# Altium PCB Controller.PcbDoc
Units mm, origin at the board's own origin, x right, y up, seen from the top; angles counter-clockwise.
Board outline 154.94 x 111.76 mm, 2 copper layers (Top Layer, Bottom Layer); 187 components, 89 nets, 478 pads, 4 vias.
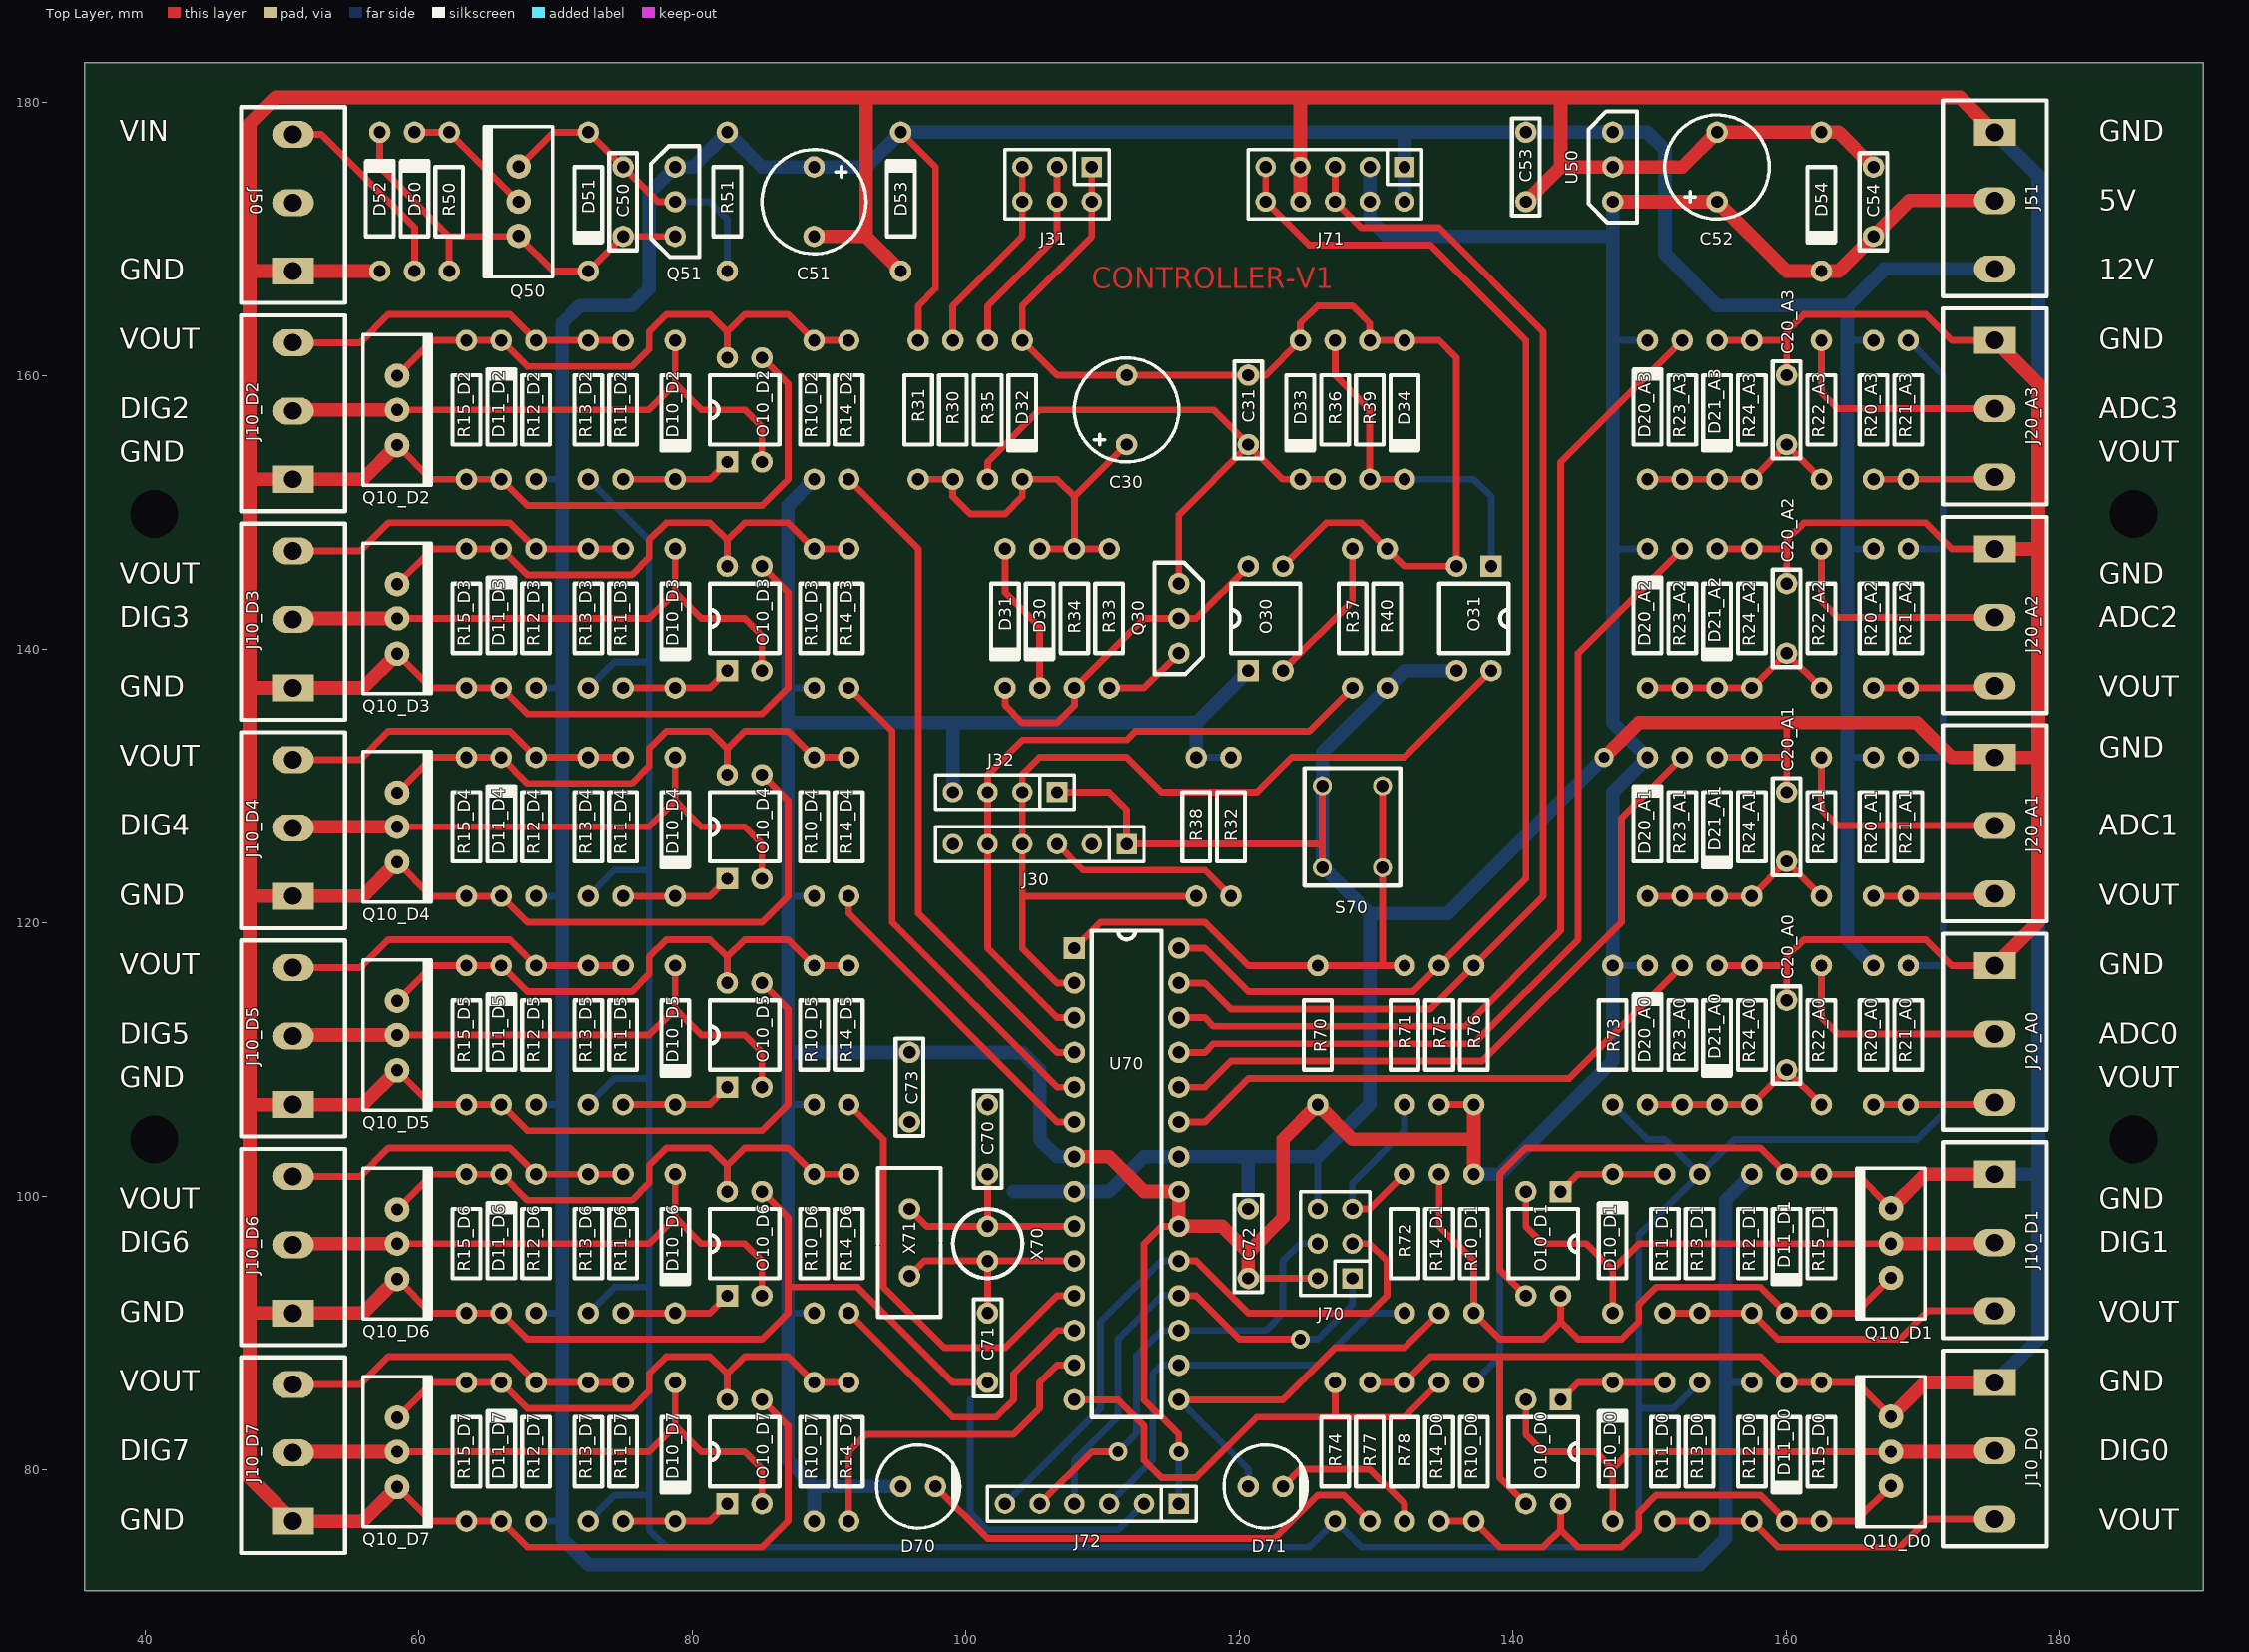
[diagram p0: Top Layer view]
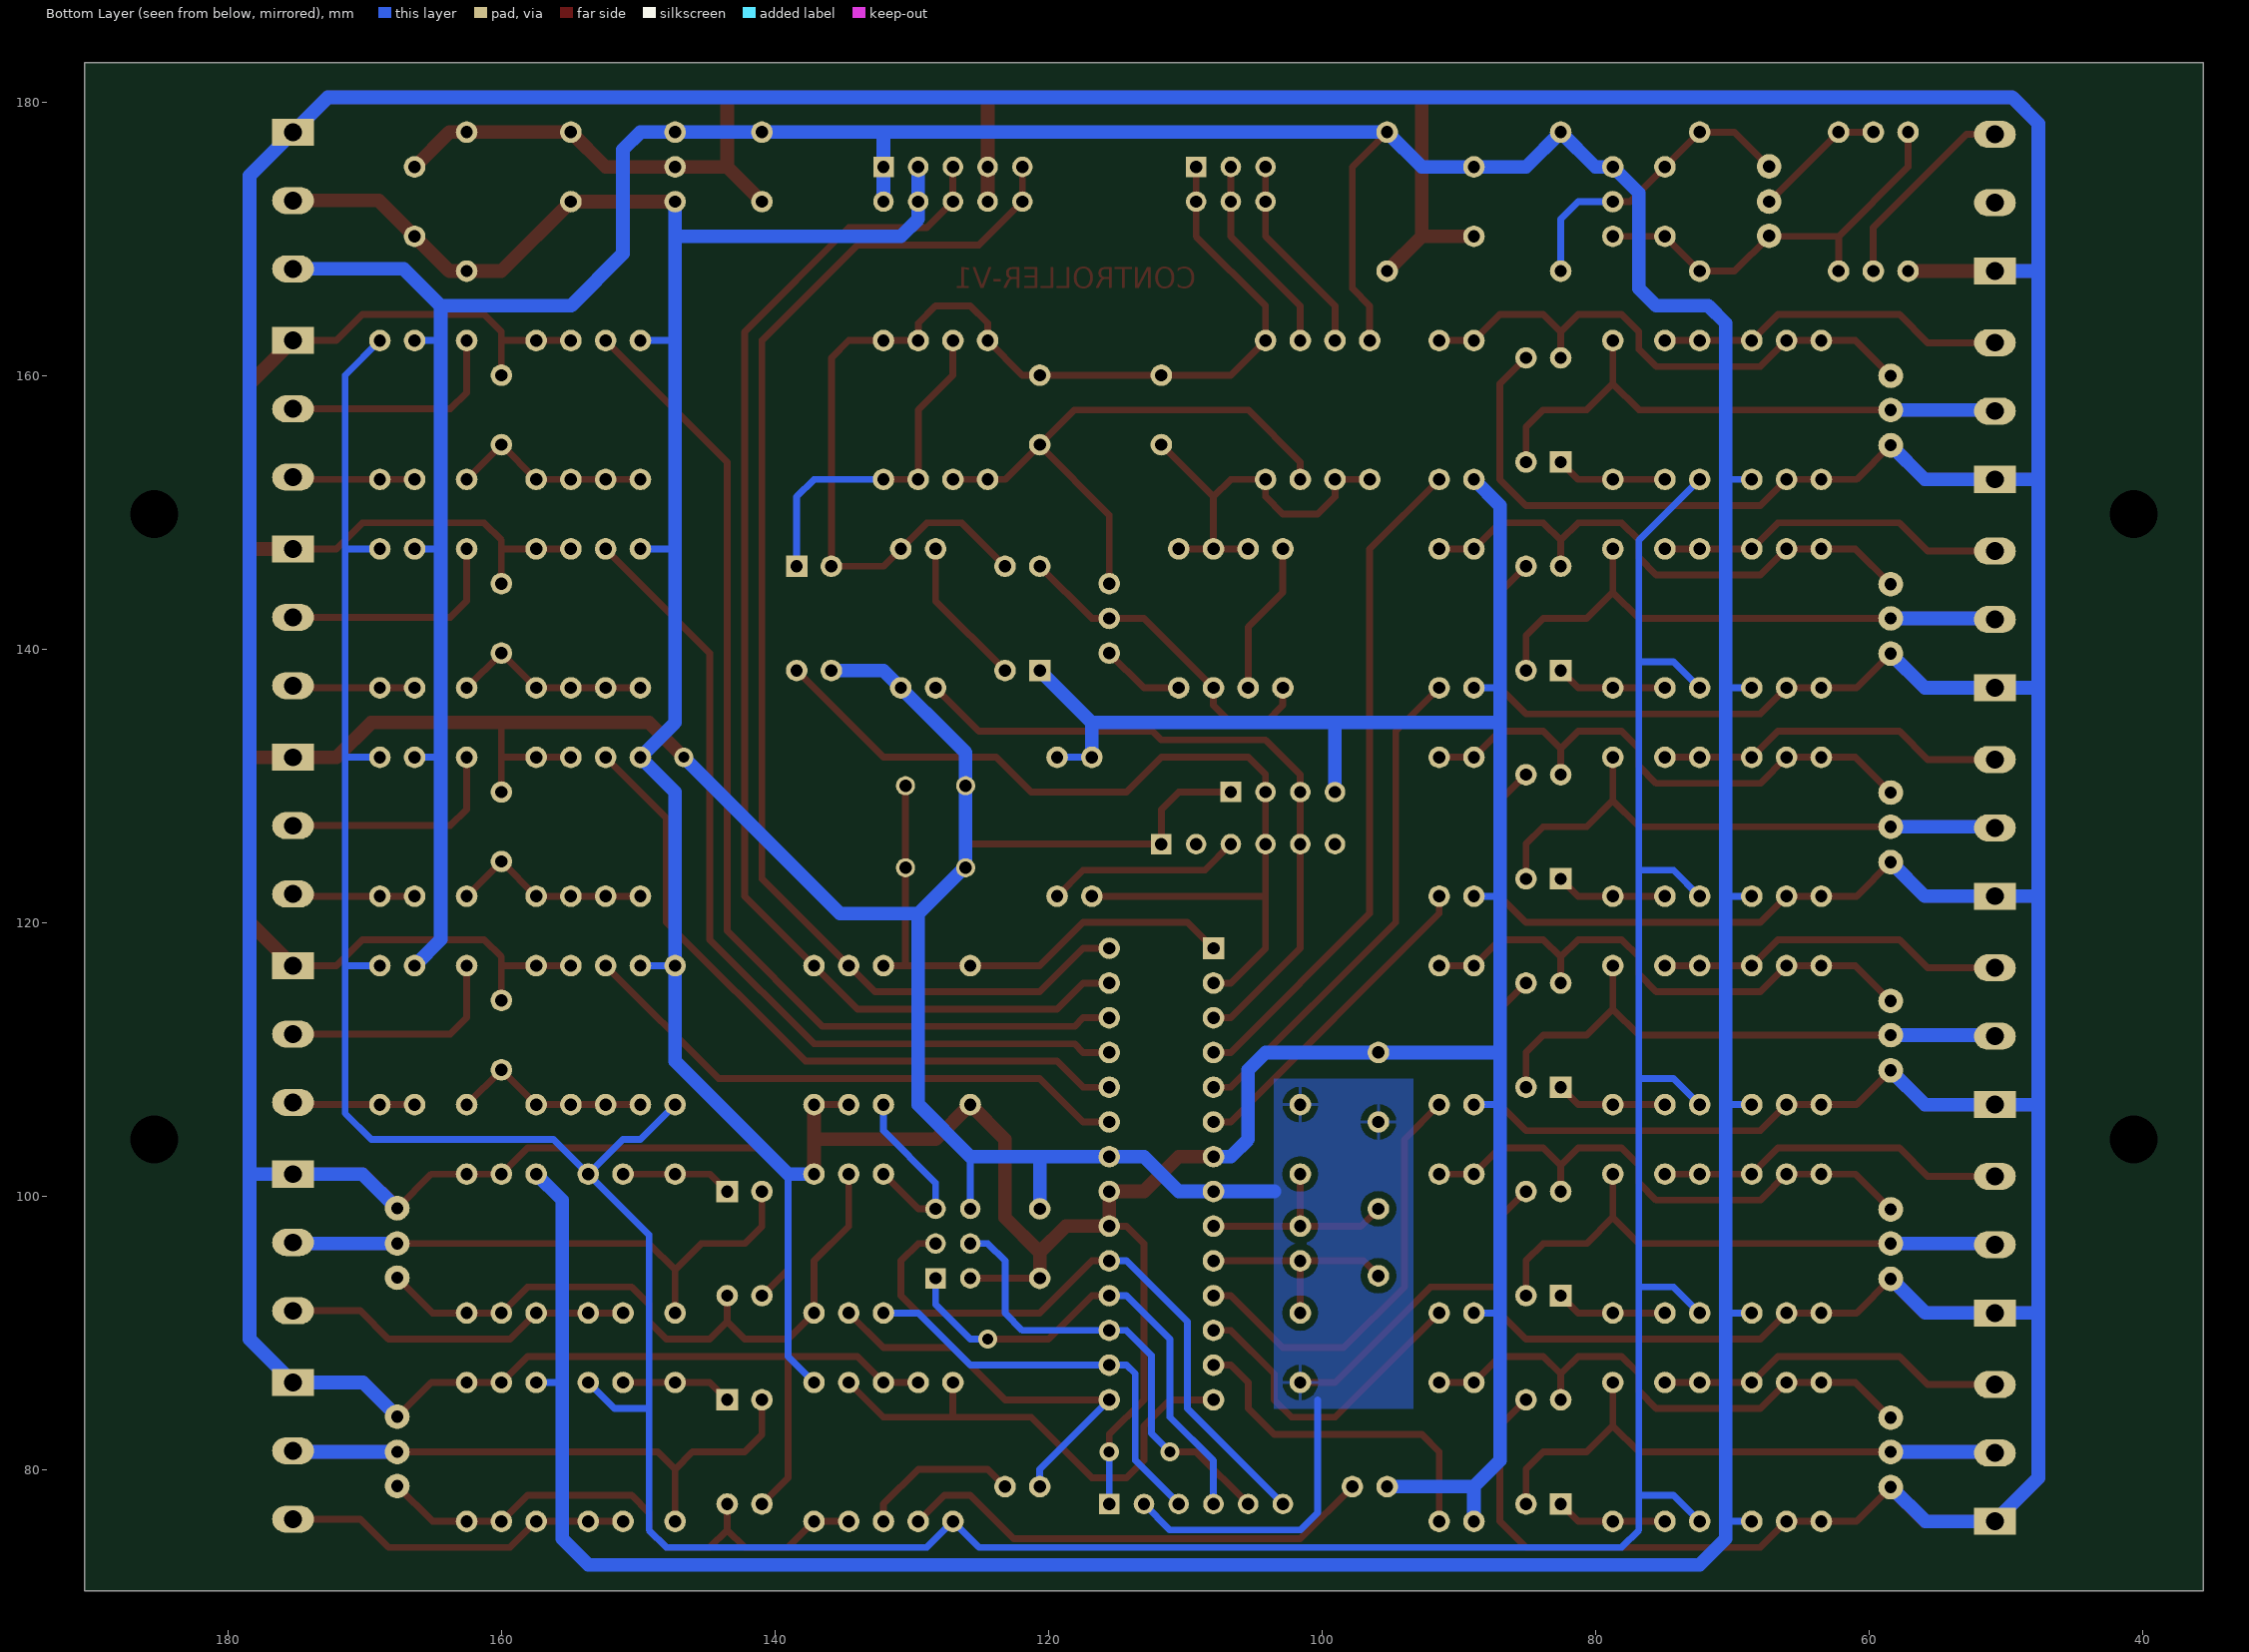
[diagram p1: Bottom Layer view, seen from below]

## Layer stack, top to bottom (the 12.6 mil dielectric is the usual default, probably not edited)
Top Layer: signal copper 0.0356
Dielectric: dielectric 0.32, FR-4, Dk 4.8
Bottom Layer: signal copper 0.0356

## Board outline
35.56,71.12 190.5,71.12 190.5,182.88 35.56,182.88

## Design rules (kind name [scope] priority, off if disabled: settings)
Clearance [All] p1: gap=0.5
ComponentClearance [All] p1: gap=0.127 collisioncheckmode=3 verticalgap=0.254
HoleSize [All] p1: absolutevalues=TRUE maxlimit=5 minlimit=0.025 maxpercent=80.000 minpercent=20.000
PolygonConnect [All] p1: connectstyle=Relief reliefconductorwidth=0.254 reliefentries=4 polygonreliefangle="90 Angle"
RoomDefinition M0 [InComponentClass('M0')] p1: confinementstyle=ConfineIn formatcopy=TRUE lockcomponents=FALSE outline 92.71,73.66 149.86,73.66 149.86,182.88 92.71,182.88
RoomDefinition P0 [InComponentClass('P0')] p2: confinementstyle=ConfineIn formatcopy=TRUE lockcomponents=FALSE outline 45.72,165.1 180.34,165.1 180.34,180.34 45.72,180.34
RoomDefinition A0 [InComponentClass('A0')] p3: confinementstyle=ConfineIn formatcopy=TRUE lockcomponents=FALSE outline 180.34,119.38 147.32,119.38 147.32,104.14 180.34,104.14
RoomDefinition A1 [InComponentClass('A1')] p4: confinementstyle=ConfineIn formatcopy=TRUE lockcomponents=FALSE outline 180.34,134.62 147.32,134.62 147.32,119.38 180.34,119.38
RoomDefinition A2 [InComponentClass('A2')] p5: confinementstyle=ConfineIn formatcopy=TRUE lockcomponents=FALSE outline 180.34,149.86 147.32,149.86 147.32,134.62 180.34,134.62
RoomDefinition A3 [InComponentClass('A3')] p6: confinementstyle=ConfineIn formatcopy=TRUE lockcomponents=FALSE outline 180.34,165.1 147.32,165.1 147.32,149.86 180.34,149.86
RoomDefinition D0 [InComponentClass('D0')] p7: confinementstyle=ConfineIn formatcopy=TRUE lockcomponents=FALSE outline 180.34,88.9 132.08,88.9 132.08,73.66 180.34,73.66
RoomDefinition D1 [InComponentClass('D1')] p8: confinementstyle=ConfineIn formatcopy=TRUE lockcomponents=FALSE outline 180.34,104.14 132.08,104.14 132.08,88.9 180.34,88.9
RoomDefinition D2 [InComponentClass('D2')] p9: confinementstyle=ConfineIn formatcopy=TRUE lockcomponents=FALSE outline 45.72,149.86 93.98,149.86 93.98,165.1 45.72,165.1
RoomDefinition D3 [InComponentClass('D3')] p10: confinementstyle=ConfineIn formatcopy=TRUE lockcomponents=FALSE outline 45.72,134.62 93.98,134.62 93.98,149.86 45.72,149.86
RoomDefinition D4 [InComponentClass('D4')] p11: confinementstyle=ConfineIn formatcopy=TRUE lockcomponents=FALSE outline 45.72,119.38 93.98,119.38 93.98,134.62 45.72,134.62
RoomDefinition D5 [InComponentClass('D5')] p12: confinementstyle=ConfineIn formatcopy=TRUE lockcomponents=FALSE outline 45.72,104.14 92.71,104.14 92.71,119.38 45.72,119.38
RoomDefinition D6 [InComponentClass('D6')] p13: confinementstyle=ConfineIn formatcopy=TRUE lockcomponents=FALSE outline 45.72,88.9 92.71,88.9 92.71,104.14 45.72,104.14
RoomDefinition D7 [InComponentClass('D7')] p14: confinementstyle=ConfineIn formatcopy=TRUE lockcomponents=FALSE outline 45.72,73.66 92.71,73.66 92.71,88.9 45.72,88.9
RoomDefinition C0 [InComponentClass('C0')] p15: confinementstyle=ConfineIn formatcopy=TRUE lockcomponents=FALSE outline 146.05,114.3 146.05,177.8 82.55,177.8 82.55,114.3
RoutingVias [All] p1: holewidth=0.8 width=1.4 viastyle="Through Hole" minholewidth=0.8 minwidth=1.4 maxholewidth=0.8 maxwidth=1.4
SolderMaskExpansion [All] p1: expansion=0.102
TestPointUsage [All] p1: valid=0 allowmultiple=FALSE
Testpoint [All] p1: side=15 testpointundercomponent=TRUE minsize=1.016 maxsize=2.54 preferedsize=1.524 minholesize=0 maxholesize=1.016 preferedholesize=0.813 testpointgrid=0.025 style=1023 order=0-112345678
Width [All] p1: maxlimit=5 minlimit=0.5 preferedwidth=0.5
17 further rules are at their usual default settings.

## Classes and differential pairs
component class P0: C50 C51 C52 C53 C54 D50 D51 D52 D53 D54 J50 J51 Q50 Q51 R50 R51 U50
component class M0: C70 C71 C72 C73 D70 D71 J70 J71 J72 R70 R71 R72 R73 R74 R75 R76 R77 R78 S70 U70 X70 X71
component class D7: D10_D7 D11_D7 J10_D7 O10_D7 Q10_D7 R10_D7 R11_D7 R12_D7 R13_D7 R14_D7 R15_D7
component class D6: D10_D6 D11_D6 J10_D6 O10_D6 Q10_D6 R10_D6 R11_D6 R12_D6 R13_D6 R14_D6 R15_D6
component class D5: D10_D5 D11_D5 J10_D5 O10_D5 Q10_D5 R10_D5 R11_D5 R12_D5 R13_D5 R14_D5 R15_D5
component class D4: D10_D4 D11_D4 J10_D4 O10_D4 Q10_D4 R10_D4 R11_D4 R12_D4 R13_D4 R14_D4 R15_D4
component class D3: D10_D3 D11_D3 J10_D3 O10_D3 Q10_D3 R10_D3 R11_D3 R12_D3 R13_D3 R14_D3 R15_D3
component class D2: D10_D2 D11_D2 J10_D2 O10_D2 Q10_D2 R10_D2 R11_D2 R12_D2 R13_D2 R14_D2 R15_D2
component class D1: D10_D1 D11_D1 J10_D1 O10_D1 Q10_D1 R10_D1 R11_D1 R12_D1 R13_D1 R14_D1 R15_D1
component class D0: D10_D0 D11_D0 J10_D0 O10_D0 Q10_D0 R10_D0 R11_D0 R12_D0 R13_D0 R14_D0 R15_D0
component class C0: C30 C31 D30 D31 D32 D33 D34 J30 J31 J32 O30 O31 Q30 R30 R31 R32 R33 R34 R35 R36 R37 R38 R39 R40
component class A3: C20_A3 D20_A3 D21_A3 J20_A3 R20_A3 R21_A3 R22_A3 R23_A3 R24_A3
component class A2: C20_A2 D20_A2 D21_A2 J20_A2 R20_A2 R21_A2 R22_A2 R23_A2 R24_A2
component class A1: C20_A1 D20_A1 D21_A1 J20_A1 R20_A1 R21_A1 R22_A1 R23_A1 R24_A1
component class A0: C20_A0 D20_A0 D21_A0 J20_A0 R20_A0 R21_A0 R22_A0 R23_A0 R24_A0
channel class Analog: A0 A1 A2 A3
channel class Digital: D0 D1 D2 D3 D4 D5 D6 D7

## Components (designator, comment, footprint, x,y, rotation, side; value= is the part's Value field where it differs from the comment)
C20_A0 "100N" AXIAL02 160.02,109.22 r90 top (schematic designator C20)
C20_A1 "100N" AXIAL02 160.02,124.46 r90 top (schematic designator C20)
C20_A2 "100N" AXIAL02 160.02,139.7 r90 top (schematic designator C20)
C20_A3 "100N" AXIAL02 160.02,154.94 r90 top (schematic designator C20)
C30 "10U" RADIAL02P 111.76,154.94 r90 top
C31 "100P" AXIAL02 120.65,154.94 r90 top
C50 "100N" AXIAL02 74.93,170.18 r90 top
C51 "10U" RADIAL02P 88.9,175.26 r270 top
C52 "10U" RADIAL02P 154.94,172.72 r90 top
C53 "100N" AXIAL02 140.97,177.8 r270 top
C54 "100N" AXIAL02 166.37,170.18 r90 top
C70 "18P" AXIAL02 101.6,101.6 r90 top
C71 "18P" AXIAL02 101.6,91.44 r270 top
C72 "100N" AXIAL02 120.65,93.98 r90 top
C73 "100N" AXIAL02 95.885,110.49 r270 top
D10_D0 "D-1N4148" DO35S 147.32,76.2 r90 top (schematic designator D10)
D10_D1 "D-1N4148" DO35S 147.32,91.44 r90 top (schematic designator D10)
D10_D2 "D-1N4148" DO35S 78.74,162.56 r270 top (schematic designator D10)
D10_D3 "D-1N4148" DO35S 78.74,147.32 r270 top (schematic designator D10)
D10_D4 "D-1N4148" DO35S 78.74,132.08 r270 top (schematic designator D10)
D10_D5 "D-1N4148" DO35S 78.74,116.84 r270 top (schematic designator D10)
D10_D6 "D-1N4148" DO35S 78.74,101.6 r270 top (schematic designator D10)
D10_D7 "D-1N4148" DO35S 78.74,86.36 r270 top (schematic designator D10)
D11_D0 "5V6" DO35S 160.02,86.36 r270 top (schematic designator D11)
D11_D1 "5V6" DO35S 160.02,101.6 r270 top (schematic designator D11)
D11_D2 "5V6" DO35S 66.04,152.4 r90 top (schematic designator D11)
D11_D3 "5V6" DO35S 66.04,137.16 r90 top (schematic designator D11)
D11_D4 "5V6" DO35S 66.04,121.92 r90 top (schematic designator D11)
D11_D5 "5V6" DO35S 66.04,106.68 r90 top (schematic designator D11)
D11_D6 "5V6" DO35S 66.04,91.44 r90 top (schematic designator D11)
D11_D7 "5V6" DO35S 66.04,76.2 r90 top (schematic designator D11)
D20_A0 "D-1N4148" DO35S 149.86,106.68 r90 top (schematic designator D20)
D20_A1 "D-1N4148" DO35S 149.86,121.92 r90 top (schematic designator D20)
D20_A2 "D-1N4148" DO35S 149.86,137.16 r90 top (schematic designator D20)
D20_A3 "D-1N4148" DO35S 149.86,152.4 r90 top (schematic designator D20)
D21_A0 "D-1N4148" DO35S 154.94,116.84 r270 top (schematic designator D21)
D21_A1 "D-1N4148" DO35S 154.94,132.08 r270 top (schematic designator D21)
D21_A2 "D-1N4148" DO35S 154.94,147.32 r270 top (schematic designator D21)
D21_A3 "D-1N4148" DO35S 154.94,162.56 r270 top (schematic designator D21)
D30 "D-1N4148" DO35S 105.41,147.32 r270 top
D31 "D-1N4148" DO35S 102.87,147.32 r270 top
D32 "15V" DO35S 104.14,162.56 r270 top
D33 "5V6" DO35S 124.46,162.56 r270 top
D34 "D-1N4148" DO35S 132.08,162.56 r270 top
D50 "D-1N4001" DO35S 59.69,167.64 r90 top
D51 "12V" DO35S 72.39,177.8 r270 top
D52 "15V" DO35S 57.15,167.64 r90 top
D53 "15V" DO35S 95.25,167.64 r90 top
D54 "5V6" DO35S 162.56,177.8 r270 top
D70 "RED" LED5MM 96.52,78.74 r0 top
D71 "AMBER" LED5MM 121.92,78.74 r0 top
J10_D0 "TERM" MKD500S3 175.26,86.36 r270 top (schematic designator J10)
J10_D1 "TERM" MKD500S3 175.26,101.6 r270 top (schematic designator J10)
J10_D2 "TERM" MKD500S3 50.8,152.4 r90 top (schematic designator J10)
J10_D3 "TERM" MKD500S3 50.8,137.16 r90 top (schematic designator J10)
J10_D4 "TERM" MKD500S3 50.8,121.92 r90 top (schematic designator J10)
J10_D5 "TERM" MKD500S3 50.8,106.68 r90 top (schematic designator J10)
J10_D6 "TERM" MKD500S3 50.8,91.44 r90 top (schematic designator J10)
J10_D7 "TERM" MKD500S3 50.8,76.2 r90 top (schematic designator J10)
J20_A0 "TERM" MKD500S3 175.26,116.84 r270 top (schematic designator J20)
J20_A1 "TERM" MKD500S3 175.26,132.08 r270 top (schematic designator J20)
J20_A2 "TERM" MKD500S3 175.26,147.32 r270 top (schematic designator J20)
J20_A3 "TERM" MKD500S3 175.26,162.56 r270 top (schematic designator J20)
J30 "HDR1X6" HDR6X1 111.76,125.73 r180 top
J31 "HDR3X2" HDR3X2 109.22,175.26 r180 top
J32 "HDR1X4" HDR4X1 106.68,129.54 r180 top
J50 "TERM" MKD500S3 50.8,167.64 r90 top
J51 "TERM" MKD500S3 175.26,177.8 r270 top
J70 "HDR3X2" HDR3X2 128.27,93.98 r90 top
J71 "HDR5X2" HDR5X2 132.08,175.26 r180 top
J72 "HDR1X6" HDR6X1 115.57,77.47 r180 top
O10_D0 "FOD817B" DIP4 143.51,85.09 r270 top (schematic designator O10)
O10_D1 "FOD817B" DIP4 143.51,100.33 r270 top (schematic designator O10)
O10_D2 "FOD817B" DIP4 82.55,153.67 r90 top (schematic designator O10)
O10_D3 "FOD817B" DIP4 82.55,138.43 r90 top (schematic designator O10)
O10_D4 "FOD817B" DIP4 82.55,123.19 r90 top (schematic designator O10)
O10_D5 "FOD817B" DIP4 82.55,107.95 r90 top (schematic designator O10)
O10_D6 "FOD817B" DIP4 82.55,92.71 r90 top (schematic designator O10)
O10_D7 "FOD817B" DIP4 82.55,77.47 r90 top (schematic designator O10)
O30 "FOD817B" DIP4 120.65,138.43 r90 top
O31 "FOD817B" DIP4 138.43,146.05 r270 top
Q10_D0 "FQPF10N20C" TO220V 167.64,81.28 r90 top (schematic designator Q10)
Q10_D1 "FQPF10N20C" TO220V 167.64,96.52 r90 top (schematic designator Q10)
Q10_D2 "FQPF10N20C" TO220V 58.42,157.48 r270 top (schematic designator Q10)
Q10_D3 "FQPF10N20C" TO220V 58.42,142.24 r270 top (schematic designator Q10)
Q10_D4 "FQPF10N20C" TO220V 58.42,127 r270 top (schematic designator Q10)
Q10_D5 "FQPF10N20C" TO220V 58.42,111.76 r270 top (schematic designator Q10)
Q10_D6 "FQPF10N20C" TO220V 58.42,96.52 r270 top (schematic designator Q10)
Q10_D7 "FQPF10N20C" TO220V 58.42,81.28 r270 top (schematic designator Q10)
Q30 "Q-BC558" TO92 115.57,139.7 r90 top
Q50 "FQPF10N20C" TO220V 67.31,172.72 r90 top
Q51 "BC548" TO92 78.74,175.26 r270 top
R10_D0 "4K7" AXIAL04 137.16,76.2 r90 top (schematic designator R10)
R10_D1 "4K7" AXIAL04 137.16,91.44 r90 top (schematic designator R10)
R10_D2 "4K7" AXIAL04 88.9,162.56 r270 top (schematic designator R10)
R10_D3 "4K7" AXIAL04 88.9,147.32 r270 top (schematic designator R10)
R10_D4 "4K7" AXIAL04 88.9,132.08 r270 top (schematic designator R10)
R10_D5 "4K7" AXIAL04 88.9,116.84 r270 top (schematic designator R10)
R10_D6 "4K7" AXIAL04 88.9,101.6 r270 top (schematic designator R10)
R10_D7 "4K7" AXIAL04 88.9,86.36 r270 top (schematic designator R10)
R11_D0 "33R" AXIAL04 151.13,86.36 r270 top (schematic designator R11)
R11_D1 "33R" AXIAL04 151.13,101.6 r270 top (schematic designator R11)
R11_D2 "33R" AXIAL04 74.93,152.4 r90 top (schematic designator R11)
R11_D3 "33R" AXIAL04 74.93,137.16 r90 top (schematic designator R11)
R11_D4 "33R" AXIAL04 74.93,121.92 r90 top (schematic designator R11)
R11_D5 "33R" AXIAL04 74.93,106.68 r90 top (schematic designator R11)
R11_D6 "33R" AXIAL04 74.93,91.44 r90 top (schematic designator R11)
R11_D7 "33R" AXIAL04 74.93,76.2 r90 top (schematic designator R11)
R12_D0 "33R" AXIAL04 157.48,76.2 r90 top (schematic designator R12)
R12_D1 "33R" AXIAL04 157.48,91.44 r90 top (schematic designator R12)
R12_D2 "33R" AXIAL04 68.58,162.56 r270 top (schematic designator R12)
R12_D3 "33R" AXIAL04 68.58,147.32 r270 top (schematic designator R12)
R12_D4 "33R" AXIAL04 68.58,132.08 r270 top (schematic designator R12)
R12_D5 "33R" AXIAL04 68.58,116.84 r270 top (schematic designator R12)
R12_D6 "33R" AXIAL04 68.58,101.6 r270 top (schematic designator R12)
R12_D7 "33R" AXIAL04 68.58,86.36 r270 top (schematic designator R12)
R13_D0 "33R" AXIAL04 153.67,76.2 r90 top (schematic designator R13)
R13_D1 "33R" AXIAL04 153.67,91.44 r90 top (schematic designator R13)
R13_D2 "33R" AXIAL04 72.39,162.56 r270 top (schematic designator R13)
R13_D3 "33R" AXIAL04 72.39,147.32 r270 top (schematic designator R13)
R13_D4 "33R" AXIAL04 72.39,132.08 r270 top (schematic designator R13)
R13_D5 "33R" AXIAL04 72.39,116.84 r270 top (schematic designator R13)
R13_D6 "33R" AXIAL04 72.39,101.6 r270 top (schematic designator R13)
R13_D7 "33R" AXIAL04 72.39,86.36 r270 top (schematic designator R13)
R14_D0 "3K3" AXIAL04 134.62,76.2 r90 top (schematic designator R14)
R14_D1 "3K3" AXIAL04 134.62,101.6 r270 top (schematic designator R14)
R14_D2 "3K3" AXIAL04 91.44,162.56 r270 top (schematic designator R14)
R14_D3 "3K3" AXIAL04 91.44,147.32 r270 top (schematic designator R14)
R14_D4 "3K3" AXIAL04 91.44,132.08 r270 top (schematic designator R14)
R14_D5 "3K3" AXIAL04 91.44,116.84 r270 top (schematic designator R14)
R14_D6 "3K3" AXIAL04 91.44,101.6 r270 top (schematic designator R14)
R14_D7 "3K3" AXIAL04 91.44,86.36 r270 top (schematic designator R14)
R15_D0 "100K" AXIAL04 162.56,86.36 r270 top (schematic designator R15)
R15_D1 "100K" AXIAL04 162.56,101.6 r270 top (schematic designator R15)
R15_D2 "100K" AXIAL04 63.5,152.4 r90 top (schematic designator R15)
R15_D3 "100K" AXIAL04 63.5,137.16 r90 top (schematic designator R15)
R15_D4 "100K" AXIAL04 63.5,121.92 r90 top (schematic designator R15)
R15_D5 "100K" AXIAL04 63.5,106.68 r90 top (schematic designator R15)
R15_D6 "100K" AXIAL04 63.5,91.44 r90 top (schematic designator R15)
R15_D7 "100K" AXIAL04 63.5,76.2 r90 top (schematic designator R15)
R20_A0 "33R" AXIAL04 166.37,106.68 r90 top (schematic designator R20)
R20_A1 "33R" AXIAL04 166.37,121.92 r90 top (schematic designator R20)
R20_A2 "33R" AXIAL04 166.37,137.16 r90 top (schematic designator R20)
R20_A3 "33R" AXIAL04 166.37,152.4 r90 top (schematic designator R20)
R21_A0 "33R" AXIAL04 168.91,106.68 r90 top (schematic designator R21)
R21_A1 "33R" AXIAL04 168.91,121.92 r90 top (schematic designator R21)
R21_A2 "33R" AXIAL04 168.91,137.16 r90 top (schematic designator R21)
R21_A3 "33R" AXIAL04 168.91,152.4 r90 top (schematic designator R21)
R22_A0 "33R" AXIAL04 162.56,106.68 r90 top (schematic designator R22)
R22_A1 "33R" AXIAL04 162.56,121.92 r90 top (schematic designator R22)
R22_A2 "33R" AXIAL04 162.56,137.16 r90 top (schematic designator R22)
R22_A3 "33R" AXIAL04 162.56,152.4 r90 top (schematic designator R22)
R23_A0 "1K" AXIAL04 152.4,106.68 r90 top (schematic designator R23)
R23_A1 "1K" AXIAL04 152.4,121.92 r90 top (schematic designator R23)
R23_A2 "1K" AXIAL04 152.4,137.16 r90 top (schematic designator R23)
R23_A3 "1K" AXIAL04 152.4,152.4 r90 top (schematic designator R23)
R24_A0 "33R" AXIAL04 157.48,116.84 r270 top (schematic designator R24)
R24_A1 "33R" AXIAL04 157.48,132.08 r270 top (schematic designator R24)
R24_A2 "33R" AXIAL04 157.48,147.32 r270 top (schematic designator R24)
R24_A3 "33R" AXIAL04 157.48,162.56 r270 top (schematic designator R24)
R30 "33R" AXIAL04 99.06,162.56 r270 top
R31 "33R" AXIAL04 96.52,152.4 r90 top
R32 "33R" AXIAL04 119.38,121.92 r90 top
R33 "33R" AXIAL04 110.49,137.16 r90 top
R34 "1K5" AXIAL04 107.95,137.16 r90 top
R35 "33R" AXIAL04 101.6,162.56 r270 top
R36 "3K3" AXIAL04 127,162.56 r270 top
R37 "3K3" AXIAL04 128.27,137.16 r90 top
R38 "4K7" AXIAL04 116.84,121.92 r90 top
R39 "1K5" AXIAL04 129.54,162.56 r270 top
R40 "33R" AXIAL04 130.81,147.32 r270 top
R50 "100K" AXIAL04 62.23,167.64 r90 top
R51 "10R" AXIAL04 82.55,177.8 r270 top
R70 "10K" AXIAL04 125.73,116.84 r270 top
R71 "33R" AXIAL04 132.08,116.84 r270 top
R72 "33R" AXIAL04 132.08,91.44 r90 top
R73 "33R" AXIAL04 147.32,106.68 r90 top
R74 "33R" AXIAL04 127,76.2 r90 top
R75 "1K" AXIAL04 134.62,116.84 r270 top
R76 "1K" AXIAL04 137.16,116.84 r270 top
R77 "1K" AXIAL04 129.54,86.36 r270 top
R78 "1K" AXIAL04 132.08,86.36 r270 top
S70 "S-BUTTON" SWPB 128.27,127 r0 top
U50 "LP2950-5V" TO92 147.32,177.8 r270 top
U70 "ATMEGA8" DIP28N 107.95,118.11 r0 top
X70 "32.768K" RADIAL01 101.6,97.79 r270 top
X71 "4M" HC49 95.885,99.06 r270 top

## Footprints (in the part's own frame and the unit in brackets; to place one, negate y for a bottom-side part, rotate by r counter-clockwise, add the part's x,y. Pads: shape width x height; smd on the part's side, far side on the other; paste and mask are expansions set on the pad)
AXIAL02 [mil]
  round 62 hole 35.43: 1(0,0) 2(200,0)
  silkscreen extent -40,-40 240,40
AXIAL04 [mil]
  round 62 hole 35.43: 1(0,0) 2(400,0)
  silkscreen extent 100,-40 300,40
DIP4 [mil]
  rect 62x62 hole 35.43: 1(0,0)
  round 62 hole 35.43: 2(0,-100) 3(300,-100) 4(300,0)
  silkscreen extent 50,-150 250,50
DIP28N [mil]
  rect 62x62 hole 35.43: 1(0,0)
  round 62 hole 35.43: 2(0,-100) 3(0,-200) 4(0,-300) 5(0,-400) 6(0,-500) 7(0,-600) 8(0,-700) 9(0,-800) 10(0,-900) 11(0,-1000) 12(0,-1100) 13(0,-1200) 14(0,-1300) 15(300,-1300) 16(300,-1200) 17(300,-1100) 18(300,-1000) 19(300,-900) 20(300,-800) 21(300,-700) 22(300,-600) 23(300,-500) 24(300,-400) 25(300,-300) 26(300,-200) 27(300,-100) 28(300,0)
  silkscreen extent 50,-1350 250,50
DO35S [mil]
  round 62 hole 35.43: 1(0,0) 2(400,0)
  silkscreen extent 100,-40 317,40
HC49 [mil]
  round 62 hole 35.43: 1(0,0) 2(192.91,0)
  silkscreen extent -118,-91 311,91
HDR3X2 [mm] "Header 3 x 2"
  rect 1.5x1.5 hole 0.9: 1(0,0)
  round 1.5 hole 0.9: 2(0,2.54) 3(2.54,0) 4(2.54,2.54) 5(5.08,0) 6(5.08,2.54)
  silkscreen extent -1.27,-1.27 6.35,3.81
HDR4X1 [mm] "Header 4 x 1"
  rect 1.5x1.5 hole 0.9: 1(0,0)
  round 1.5 hole 0.9: 2(2.54,0) 3(5.08,0) 4(7.62,0)
  silkscreen extent -1.27,-1.27 8.9,1.27
HDR5X2 [mm] "Header 5 x 2"
  rect 1.5x1.5 hole 0.9: 1(0,0)
  round 1.5 hole 0.9: 2(0,2.54) 3(2.54,0) 4(2.54,2.54) 5(5.08,0) 6(5.08,2.54) 7(7.62,0) 8(7.62,2.54) 9(10.16,0) 10(10.16,2.54)
  silkscreen extent -1.27,-1.27 11.43,3.81
HDR6X1 [mm] "Header 6 x 1"
  rect 1.5x1.5 hole 0.9: 1(0,0)
  round 1.5 hole 0.9: 2(2.54,0) 3(5.08,0) 4(7.62,0) 5(10.16,0) 6(12.7,0)
  silkscreen extent -1.27,-1.27 13.97,1.27
LED5MM [mil]
  round 62 hole 35.43: 1(-50,0) 2(50,0)
  silkscreen extent -120,-120 120,120
MKD500S3 [mil]
  rect 78x120 hole 51.18: 1(0,0)
  oval 78x120 hole 51.18: 2(196.85,0) 3(393.7,0)
  silkscreen extent -92,-150 472,150
RADIAL01 [mil]
  round 62 hole 35.43: 1(0,0) 2(100,0)
  silkscreen extent -50,-100 150,100
RADIAL02P [mil]
  round 62 hole 35.43: 1(0,0) 2(200,0)
  silkscreen extent -50,-150 250,150
SWPB [mm]
  round 1.4 hole 0.9: 1(-2.2,3) 2(2.2,3) 3(-2.2,-3) 4(2.2,-3)
  silkscreen extent -3.5,-4.3 3.5,4.3
TO92 [mil]
  round 62 hole 35.43: 1(0,0) 2(100,0) 3(200,0)
  silkscreen extent -60,-70 260,70
TO220V [mm] "TO220"
  round 1.8 hole 0.9: 1(-2.5,0) 2(0,0) 3(2.58,0)
  silkscreen extent -5.5,-2.5 5.5,2.5

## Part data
C20_A0 C20_A1 C20_A2 C20_A3 C50 C53 C54 C72 C73: library part C-B100N, "CAPACITOR"
C30 C51 C52: library part C-A10U, "CAP"
C31: library part C-B100P, "CAPACITOR"
C70 C71: library part C-B18P, "CAPACITOR"
D10_D0 D10_D1 D10_D2 D10_D3 D10_D4 D10_D5 D10_D6 D10_D7 D20_A0 D20_A1 D20_A2 D20_A3 D21_A0 D21_A1 D21_A2 D21_A3 D30 D31 D34: "1N4148"
D11_D0 D11_D1 D11_D2 D11_D3 D11_D4 D11_D5 D11_D6 D11_D7 D51: library part D-BZX79-12, "ZENER DIODE"
D32 D52 D53: library part D-BZX79-15, "ZENER DIODE"
D33 D54: library part D-BZX79-5V6, "ZENER DIODE"
D50: "1N4001"
D70: library part O-RED, "LED"
D71: library part O-AMBER, "LED"
J10_D0 J10_D1 J10_D2 J10_D3 J10_D4 J10_D5 J10_D6 J10_D7 J20_A0 J20_A1 J20_A2 J20_A3 J50 J51: library part J-SCR-3, "CONNECTOR"
J30 J72: library part J-HDR1X6, "CONNECTOR"
J31: library part J-HDR3X2A, "CONNECTOR"
J32: library part J-HDR1X4, "CONNECTOR"
J70: library part J-HDR3X2, "CONNECTOR"
J71: library part J-HDR5X2A, "CONNECTOR"
O10_D0 O10_D1 O10_D2 O10_D3 O10_D4 O10_D5 O10_D6 O10_D7 O30 O31: library part O-FOD817B, "OPTO ISOLATOR"
Q10_D0 Q10_D1 Q10_D2 Q10_D3 Q10_D4 Q10_D5 Q10_D6 Q10_D7 Q50: library part Q-FQPF10N20C, "MOSFET"
Q30: "BC558"
Q51: library part Q-BC548
R10_D0 R10_D1 R10_D2 R10_D3 R10_D4 R10_D5 R10_D6 R10_D7 R38: library part R-A4K7, "RESISTOR"
R11_D0 R11_D1 R11_D2 R11_D3 R11_D4 R11_D5 R11_D6 R11_D7 R12_D0 R12_D1 R12_D2 R12_D3 R12_D4 R12_D5 R12_D6 R12_D7 R13_D0 R13_D1 R13_D2 R13_D3 R13_D4 R13_D5 R13_D6 R13_D7 R20_A0 R20_A1 R20_A2 R20_A3 R21_A0 R21_A1 R21_A2 R21_A3 R22_A0 R22_A1 R22_A2 R22_A3 R24_A0 R24_A1 R24_A2 R24_A3 R30 R31 R32 R33 R35 R40 R71 R72 R73 R74: library part R-A33R, "RESISTOR"
R14_D0 R14_D1 R14_D2 R14_D3 R14_D4 R14_D5 R14_D6 R14_D7 R36 R37: library part R-A3K3, "RESISTOR"
R15_D0 R15_D1 R15_D2 R15_D3 R15_D4 R15_D5 R15_D6 R15_D7 R50: library part R-A100K, "RESISTOR"
R23_A0 R23_A1 R23_A2 R23_A3 R75 R76 R77 R78: library part R-A1K, "RESISTOR"
R34 R39: library part R-A1K5, "RESISTOR"
R51: library part R-A10R, "RESISTOR"
R70: library part R-A10K, "RESISTOR"
S70: "PUSH BUTTON SWITCH"
U50: library part U-LP2950, "LP2950"
U70: library part U-ATMEGA8, "MICROCONTROLLER"
X70: library part X-32K768, "CRYSTAL"
X71: library part X-4M, "CRYSTAL"

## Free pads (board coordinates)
  round 0 hole 3.5 unplated: 0(40.64,104.14) 0(40.64,149.86) 0(185.42,104.14) 0(185.42,149.86)

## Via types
v1: diameter 1.4, hole 0.8, Top Layer to Bottom Layer, 4 vias

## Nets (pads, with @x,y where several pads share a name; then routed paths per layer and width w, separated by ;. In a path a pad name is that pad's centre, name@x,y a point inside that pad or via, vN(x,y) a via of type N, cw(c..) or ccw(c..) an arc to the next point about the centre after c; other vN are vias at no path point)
0V: C20_A0.2 C20_A1.2 C20_A2.2 C20_A3.2 C51.2 C52.2 C53.2 C54.2 C70.2 C71.2 C72.2 C73.2 D11_D0.1 D11_D1.1 D11_D2.1 D11_D3.1 D11_D4.1 D11_D5.1 D11_D6.1 D11_D7.1 D21_A0.1 D21_A1.1 D21_A2.1 D21_A3.1 D52.1 D53.1 D54.1 J10_D0.1 J10_D1.1 J10_D2.1 J10_D3.1 J10_D4.1 J10_D5.1 J10_D6.1 J10_D7.1 J20_A0.1 J20_A1.1 J20_A2.1 J20_A3.1 J30.1 J32.1 J50.1 J51.1 J70.6 J71.7 J71.8 J72.2 O10_D0.3 O10_D1.3 O10_D2.3 O10_D3.3 O10_D4.3 O10_D5.3 O10_D6.3 O10_D7.3 O31.3 Q10_D0.3 Q10_D1.3 Q10_D2.3 Q10_D3.3 Q10_D4.3 Q10_D5.3 Q10_D6.3 Q10_D7.3 R15_D0.1 R15_D1.1 R15_D2.1 R15_D3.1 R15_D4.1 R15_D5.1 R15_D6.1 R15_D7.1 R24_A0.1 R24_A1.1 R24_A2.1 R24_A3.1 R40.2 R77.1 R78.1 S70.1 S70.3 U50.2 U70.8 U70.22 | length 1479.3
  Top Layer w0.5: Q10_D7.3 60.92,76.2 D11_D7.1 67.945,74.295 85.09,74.295 86.995,76.2 86.995,83.185 O10_D7.3 ; Q10_D6.3 60.92,91.44 D11_D6.1 67.945,89.535 85.09,89.535 86.995,91.44 86.995,98.425 O10_D6.3 ; Q10_D5.3 60.92,106.68 D11_D5.1 67.945,104.775 85.09,104.775 86.995,106.68 86.995,113.665 O10_D5.3 ; Q10_D4.3 60.92,121.92 D11_D4.1 67.945,120.015 85.09,120.015 86.995,121.92 86.995,128.905 O10_D4.3 ; Q10_D3.3 60.92,137.16 D11_D3.1 67.945,135.255 85.09,135.255 86.995,137.16 86.995,144.145 O10_D3.3 ; Q10_D2.3 60.92,152.4 D11_D2.1 67.945,150.495 85.09,150.495 86.995,152.4 86.995,159.385 O10_D2.3 ; 86.995,93.345 92.075,93.345 99.06,86.36 C71.2 ; J32.1 110.49,129.54 111.76,128.27 J30.1 126.07,125.73 ; S70.3 S70.1 ; R77.1 R78.1 133.985,88.265 158.115,88.265 D11_D0.1 165.14,86.36 Q10_D0.3 ; 139.065,88.265 139.065,79.375 O10_D0.3 ; O10_D1.3 139.065,94.615 139.065,101.6 140.97,103.505 158.115,103.505 D11_D1.1 165.14,101.6 Q10_D1.3 ; D21_A0.1 160.02,116.84 ; D21_A1.1 160.02,132.08 ; D21_A2.1 160.02,147.32 ; D21_A3.1 160.02,162.56 ; C20_A0.2 160.02,117.475 161.29,118.745 170.18,118.745 172.085,116.84 J20_A0.1 ; C20_A1.2 160.02,134.62 ; C20_A2.2 160.02,147.955 161.29,149.225 170.18,149.225 172.085,147.32 J20_A2.1 ; C20_A3.2 160.02,163.195 161.29,164.465 170.18,164.465 172.085,162.56 J20_A3.1
  Top Layer w1: 47.625,91.44 55.92,91.44 Q10_D6.3 ; 47.625,106.68 55.92,106.68 Q10_D5.3 ; 47.625,121.92 55.92,121.92 Q10_D4.3 ; 47.625,137.16 55.92,137.16 Q10_D3.3 ; 47.625,152.4 55.92,152.4 Q10_D2.3 ; 47.625,167.64 D52.1 ; Q10_D7.3 55.92,76.2 J10_D7.1 47.625,79.375 47.625,178.435 49.53,180.34 172.72,180.34 J51.1 ; C51.2 92.71,170.18 ; 92.71,180.34 92.71,170.18 ; D53.1 92.71,170.18 ; J71.8 124.46,180.34 ; C53.2 143.51,175.26 ; 143.51,180.34 143.51,175.26 ; v1(146.685,132.08) 149.225,134.62 169.545,134.62 172.085,132.08 178.435,132.08 ; C54.2 163.83,177.8 C52.2 152.4,175.26 143.51,175.26 ; Q10_D0.3 170.14,86.36 J10_D0.1 ; Q10_D1.3 170.14,101.6 J10_D1.1 ; J20_A0.1 178.435,120.015 178.435,159.385 J20_A3.1 ; J20_A2.1 178.435,147.32
  Bottom Layer w0.5: 100.33,85.09 100.33,76.835 101.6,75.565 111.125,75.565 J72.2 ; J70.6 125.73,102.87
  Bottom Layer w1: 47.625,91.44 55.88,91.44 Q10_D6.3@58.42,93.98 ; 47.625,106.68 55.92,106.68 Q10_D5.3 ; 47.625,121.92 55.92,121.92 Q10_D4.3 ; 47.625,137.16 55.92,137.16 Q10_D3.3 ; 47.625,152.4 55.92,152.4 Q10_D2.3 ; 47.625,167.64 J50.1 ; Q10_D7.3 58.38,78.7 55.88,76.2 J10_D7.1 47.625,79.375 47.625,178.435 49.53,180.34 172.72,180.34 178.435,174.625 178.435,89.535 J10_D0.1 170.14,86.36 Q10_D0.3 ; 103.505,100.33 110.49,100.33 113.03,102.87 125.73,102.87 129.54,106.68 129.54,120.65 ; C72.2 120.65,102.87 ; O31.3 132.08,138.43 126.07,132.42 126.07,124.12 129.54,120.65 ; v1(146.685,132.08) 135.255,120.65 129.54,120.65 ; Q10_D1.3@167.64,99.06 170.18,101.6 178.435,101.6
5V: C52.1 C54.1 C72.1 C73.1 D20_A0.2 D20_A1.2 D20_A2.2 D20_A3.2 D54.2 D70.1 J32.4 J51.2 J70.2 J71.3 J71.4 J72.1 O30.1 R10_D0.2 R10_D1.2 R10_D2.2 R10_D3.2 R10_D4.2 R10_D5.2 R10_D6.2 R10_D7.2 R32.2 R38.2 R70.2 R73.2 R75.2 R76.2 U50.3 U70.7 U70.20 U70.21 | length 401
  Top Layer w0.5: v1(115.57,81.28) 115.57,82.55 113.03,85.09 113.03,96.52 114.3,97.79 U70.20 ; C72.1 J70.2 ; R75.2 R76.2
  Top Layer w1: U70.7 110.49,102.87 113.03,100.33 U70.21 U70.20 118.745,97.79 120.65,95.885 ; C72.1 120.65,95.885 ; R10_D1.2 R76.2 ; 137.16,104.14 128.27,104.14 R70.2 123.19,104.14 123.19,98.425 120.65,95.885 ; U50.3 C52.1 160.02,167.64 163.83,167.64 168.99,172.8 J51.2
  Bottom Layer w0.5: 86.995,91.44 R10_D6.2 ; 86.995,106.68 R10_D5.2 ; 86.995,121.92 R10_D4.2 ; 86.995,137.16 R10_D3.2 ; J72.1 v1(115.57,81.28) ; R38.2 R32.2 ; R10_D0.2 139.065,88.265 139.065,101.6 ; R73.2 D20_A0.2 ; 147.32,147.32 D20_A2.2 ; 147.32,162.56 D20_A3.2
  Bottom Layer w1: 86.995,110.49 104.14,110.49 105.41,109.22 105.41,104.14 106.68,102.87 U70.7 ; 86.995,134.62 116.84,134.62 ; R10_D7.2 88.9,78.74 ; R10_D2.2 86.995,150.495 86.995,80.645 88.9,78.74 ; D70.1 88.9,78.74 ; J32.4 99.06,134.62 ; R38.2 116.84,134.62 ; O30.1 116.84,134.62 ; J71.3 129.54,171.45 130.81,170.18 147.32,170.18 ; R10_D1.2 139.065,101.6 147.32,109.855 147.32,129.54 D20_A1.2 147.32,134.62 U50.3
5VAUX: R13_D0.2 R13_D1.2 R13_D2.2 R13_D3.2 R13_D4.2 R13_D5.2 R13_D6.2 R13_D7.2 R21_A0.2 R21_A1.2 R21_A2.2 R21_A3.2 R73.1 R74.1 | length 306.2
  Bottom Layer w0.5: R13_D7.2 74.295,78.105 76.835,78.105 ; R13_D6.2 74.295,93.345 76.835,93.345 ; R13_D5.2 74.295,108.585 76.835,108.585 ; R13_D4.2 74.295,123.825 76.835,123.825 ; R13_D3.2 74.295,139.065 76.835,139.065 ; R13_D2.2 76.835,147.955 76.835,75.565 78.105,74.295 125.095,74.295 R74.1 128.905,74.295 147.955,74.295 149.225,75.565 149.225,97.155 156.21,104.14 169.545,104.14 171.45,106.045 171.45,160.02 R21_A3.2 ; R73.1 149.86,104.14 151.13,104.14 R13_D1.2 ; 149.225,84.455 151.765,84.455 R13_D0.2 ; R21_A0.2 171.45,116.84 ; R21_A1.2 171.45,132.08 ; R21_A2.2 171.45,147.32
12V: C51.1 C53.1 D53.2 J51.3 J71.1 J71.2 Q51.1 R12_D0.2 R12_D1.2 R12_D2.2 R12_D3.2 R12_D4.2 R12_D5.2 R12_D6.2 R12_D7.2 R20_A0.2 R20_A1.2 R20_A2.2 R20_A3.2 R31.2 R51.1 U50.1 | length 420.6
  Top Layer w0.5: D53.2 97.79,175.26 97.79,166.37 96.52,165.1 R31.2
  Bottom Layer w0.5: R12_D7.2 70.485,76.2 ; R12_D6.2 70.485,91.44 ; R12_D5.2 70.485,106.68 ; R12_D4.2 70.485,121.92 ; R12_D3.2 70.485,137.16 ; R12_D2.2 70.485,152.4 ; 155.575,86.36 R12_D0.2 ; 164.465,132.08 R20_A1.2 ; 164.465,147.32 R20_A2.2 ; 164.465,162.56 R20_A3.2
  Bottom Layer w1: J71.2 132.08,177.8 ; R12_D1.2 155.575,99.695 155.575,74.93 153.67,73.025 72.39,73.025 70.485,74.93 70.485,163.83 71.755,165.1 75.565,165.1 76.835,166.37 76.835,173.355 Q51.1 80.01,175.26 R51.1 85.09,175.26 92.71,175.26 D53.2 149.86,177.8 151.13,176.53 151.13,168.91 154.94,165.1 164.465,165.1 ; R20_A0.2 164.465,118.745 164.465,165.1 ; J51.3 167.165,167.8 164.465,165.1
AIN0: R23_A0.2 U70.23 | length 41.6
  Top Layer w0.5: U70.23 117.475,105.41 120.65,108.585 144.145,108.585 R23_A0.2
AIN1: R23_A1.2 U70.24 | length 51.3
  Top Layer w0.5: U70.24 117.475,107.95 119.38,109.855 137.795,109.855 147.955,120.015 147.955,127.635 R23_A1.2
AIN2: R23_A2.2 U70.25 | length 64.4
  Top Layer w0.5: U70.25 117.475,110.49 118.11,111.125 137.16,111.125 144.78,118.745 144.78,139.7 R23_A2.2
AIN3: R23_A3.2 U70.26 | length 78
  Top Layer w0.5: U70.26 117.475,113.03 118.11,112.395 136.525,112.395 143.51,119.38 143.51,153.67 R23_A3.2
BUS-12V: J31.5 J31.6 R30.1 | length 14.8
  Top Layer w0.5: R30.1 99.06,165.1 104.14,170.18 J31.5
BUS-DATA: J31.3 J31.4 R35.1 | length 14.8
  Top Layer w0.5: R35.1 101.6,165.1 106.68,170.18 J31.3
BUS-GND: C30.2 C31.2 D32.1 D33.1 D34.1 J31.1 J31.2 O30.3 O31.2 R39.1 R40.1 | length 83.3
  Top Layer w0.5: J31.1 109.22,170.18 104.14,165.1 D32.1 106.68,160.02 121.92,160.02 D33.1 124.46,163.83 125.73,165.1 128.27,165.1 129.54,163.83 R39.1 134.62,162.56 135.89,161.29 O31.2 132.08,146.05 128.905,149.225 126.365,149.225 O30.3
BUS-RX: J30.4 J32.2 O31.4 R38.1 U70.2 | length 69.8
  Top Layer w0.5: 104.14,121.92 R38.1 ; U70.2 106.68,115.57 104.14,118.11 104.14,130.81 105.41,132.08 111.76,132.08 114.3,129.54 121.285,129.54 123.825,132.08 132.08,132.08 O31.4
BUS-TX: J30.5 J32.3 R37.1 U70.3 | length 50.5
  Top Layer w0.5: U70.3 106.68,113.03 101.6,118.11 101.6,130.81 104.14,133.35 111.76,133.35 112.395,133.985 125.095,133.985 R37.1
DIO0: R14_D0.2 R74.2 U70.14 | length 36
  Top Layer w0.5: U70.14 111.125,85.09 113.03,83.185 113.03,80.645 114.3,79.375 116.84,79.375 121.285,83.82 132.08,83.82 R14_D0.2 ; 127,83.82 R74.2
DIO1: D71.1 R14_D1.2 U70.15 | length 30.1
  Top Layer w0.5: U70.15 123.19,85.09 127,88.9 132.08,88.9 R14_D1.2
  Bottom Layer w0.5: U70.15 120.65,80.01 D71.1
DIO2: R14_D2.2 U70.4 | length 49.5
  Top Layer w0.5: R14_D2.2 96.52,147.32 96.52,120.65 106.68,110.49 U70.4
DIO3: R14_D3.2 U70.5 | length 36.8
  Top Layer w0.5: R14_D3.2 94.615,133.985 94.615,120.015 106.68,107.95 U70.5
DIO4: R14_D4.2 U70.6 | length 24.1
  Top Layer w0.5: R14_D4.2 91.44,120.65 106.68,105.41 U70.6
DIO5: R14_D5.2 U70.11 | length 31.8
  Top Layer w0.5: R14_D5.2 93.98,104.14 93.98,93.345 98.425,88.9 102.87,88.9 106.68,92.71 U70.11
DIO6: R14_D6.2 U70.12 | length 23.4
  Top Layer w0.5: R14_D6.2 99.06,83.82 102.235,83.82 103.505,85.09 103.505,86.995 106.68,90.17 U70.12
DIO7: R14_D7.2 U70.13 | length 25.3
  Top Layer w0.5: R14_D7.2 91.44,81.28 92.71,82.55 103.505,82.55 105.41,84.455 105.41,86.36 106.68,87.63 U70.13
MISO: J70.1 J72.4 U70.18 | length 36.1
  Top Layer w0.5: U70.18 116.84,92.71 120.015,89.535 v1(124.46,89.535)
  Bottom Layer w0.5: J72.4 107.95,80.645 111.125,83.82 111.125,89.535 114.3,92.71 U70.18 ; v1(124.46,89.535) 125.73,89.535 128.27,92.075 J70.1
MOSI: J70.4 J72.5 U70.17 | length 33.2
  Top Layer w0.5: J72.5 109.22,81.28 v1@110.49,81.28
  Bottom Layer w0.5: v1(111.125,81.28) 112.474,82.629 112.474,88.344 114.3,90.17 121.92,90.17 123.19,91.44 123.19,95.25 124.46,96.52 J70.4
NetC20_A0_1: C20_A0.1 D20_A0.1 D21_A0.2 R22_A0.1 R23_A0.1 R24_A0.2 | length 14.8
  Top Layer w0.5: D20_A0.1 R24_A0.2 C20_A0.1 R22_A0.1
NetC20_A1_1: C20_A1.1 D20_A1.1 D21_A1.2 R22_A1.1 R23_A1.1 R24_A1.2 | length 14.8
  Top Layer w0.5: D20_A1.1 R24_A1.2 C20_A1.1 R22_A1.1
NetC20_A2_1: C20_A2.1 D20_A2.1 D21_A2.2 R22_A2.1 R23_A2.1 R24_A2.2 | length 14.8
  Top Layer w0.5: D20_A2.1 R24_A2.2 C20_A2.1 R22_A2.1
NetC20_A3_1: C20_A3.1 D20_A3.1 D21_A3.2 R22_A3.1 R23_A3.1 R24_A3.2 | length 14.8
  Top Layer w0.5: D20_A3.1 R24_A3.2 C20_A3.1 R22_A3.1
NetC30_1: C30.1 D30.1 D32.2 R30.2 R31.1 R33.2 R34.2 | length 29.8
  Top Layer w0.5: R31.1 R30.2 99.06,151.13 100.33,149.86 102.87,149.86 104.14,151.13 D32.2 106.68,152.4 107.95,151.13 ; D30.1 R33.2 ; R34.2 107.95,151.13 ; C30.1 107.95,151.13
NetC31_1: C31.1 D33.2 Q30.3 R35.2 R36.2 | length 42.6
  Top Layer w0.5: R35.2 101.6,153.67 105.41,157.48 118.11,157.48 123.19,152.4 R36.2 ; Q30.3 115.57,149.807 C31.1@120.651,154.888
NetC50_1: C50.1 D51.2 D52.2 Q50.1 Q51.3 R50.1 | length 30.9
  Top Layer w0.5: D52.2 57.15,175.26 62.23,170.18 ; R50.1 62.23,170.18 ; Q50.1 Q50.1@67.31,170.18 ; Q51.3 C50.1 D51.2 69.85,167.64 Q50.1@67.31,170.18 ; 62.23,170.18 Q50.1@67.31,170.18
NetC50_2: C50.2 D51.1 Q50.3 Q51.2 R51.2 | length 22.7
  Top Layer w0.5: Q50.3 67.35,175.3 69.85,177.8 D51.1 77.47,172.72 Q51.2
  Bottom Layer w0.5: Q51.2 81.28,172.72 82.55,171.45 R51.2
NetC70_1: C70.1 U70.9 X70.1 X71.1 | length 16.4
  Top Layer w0.5: X71.1 97.155,97.79 U70.9 ; X70.1 C70.1
NetC71_1: C71.1 U70.10 X70.2 X71.2 | length 16.3
  Top Layer w0.5: X71.2 96.975,95.25 U70.10 ; C71.1 X70.2
NetD10_D0_1: D10_D0.1 J10_D0.2 O10_D0.2 Q10_D0.2 | length 49.7
  Top Layer w0.5: O10_D0.2 140.97,82.55 142.24,81.28 146.05,81.28 147.32,80.01 ; D10_D0.1 147.32,80.01 ; Q10_D0.2 148.59,81.28 147.32,80.01
  Top Layer w1: Q10_D0.2 J10_D0.2@175.18,81.28
  Bottom Layer w1: Q10_D0.2 J10_D0.2@175.18,81.28
NetD10_D0_2: D10_D0.2 O10_D0.1 R11_D0.1 | length 8.1
  Top Layer w0.5: O10_D0.1 144.78,86.36 R11_D0.1
NetD10_D1_1: D10_D1.1 J10_D1.2 O10_D1.2 Q10_D1.2 | length 49.6
  Top Layer w0.5: O10_D1.2 140.97,97.79 142.24,96.52 145.415,96.52 147.32,94.615 ; D10_D1.1 147.32,94.615 ; Q10_D1.2 149.225,96.52 147.32,94.615
  Top Layer w1: Q10_D1.2 J10_D1.2@175.18,96.52
  Bottom Layer w1: Q10_D1.2 J10_D1.2@175.18,96.52
NetD10_D1_2: D10_D1.2 O10_D1.1 R11_D1.1 | length 8.1
  Top Layer w0.5: O10_D1.1 144.78,101.6 R11_D1.1
NetD10_D2_1: D10_D2.1 J10_D2.2 O10_D2.2 Q10_D2.2 | length 49.6
  Top Layer w0.5: Q10_D2.2 76.835,157.48 78.74,159.385 ; D10_D2.1 78.74,159.385 ; O10_D2.2 85.09,156.21 83.82,157.48 80.645,157.48 78.74,159.385
  Top Layer w1: J10_D2.2@50.88,157.48 Q10_D2.2
  Bottom Layer w1: J10_D2.2@50.88,157.48 Q10_D2.2
NetD10_D2_2: D10_D2.2 O10_D2.1 R11_D2.1 | length 8.1
  Top Layer w0.5: R11_D2.1 81.28,152.4 O10_D2.1
NetD10_D3_1: D10_D3.1 J10_D3.2 O10_D3.2 Q10_D3.2 | length 49.6
  Top Layer w0.5: Q10_D3.2 76.835,142.24 78.74,144.145 ; D10_D3.1 78.74,144.145 ; O10_D3.2 85.09,140.97 83.82,142.24 80.645,142.24 78.74,144.145
  Top Layer w1: J10_D3.2@50.88,142.24 Q10_D3.2
  Bottom Layer w1: J10_D3.2@50.88,142.24 Q10_D3.2
NetD10_D3_2: D10_D3.2 O10_D3.1 R11_D3.1 | length 8.1
  Top Layer w0.5: R11_D3.1 81.28,137.16 O10_D3.1
NetD10_D4_1: D10_D4.1 J10_D4.2 O10_D4.2 Q10_D4.2 | length 49.6
  Top Layer w0.5: Q10_D4.2 76.835,127 78.74,128.905 ; D10_D4.1 78.74,128.905 ; O10_D4.2 85.09,125.73 83.82,127 80.645,127 78.74,128.905
  Top Layer w1: J10_D4.2@50.88,127 Q10_D4.2
  Bottom Layer w1: J10_D4.2@50.88,127 Q10_D4.2
NetD10_D4_2: D10_D4.2 O10_D4.1 R11_D4.1 | length 8.1
  Top Layer w0.5: R11_D4.1 81.28,121.92 O10_D4.1
NetD10_D5_1: D10_D5.1 J10_D5.2 O10_D5.2 Q10_D5.2 | length 49.6
  Top Layer w0.5: Q10_D5.2 76.835,111.76 78.74,113.665 ; D10_D5.1 78.74,113.665 ; O10_D5.2 85.09,110.49 83.82,111.76 80.645,111.76 78.74,113.665
  Top Layer w1: J10_D5.2@50.88,111.76 Q10_D5.2
  Bottom Layer w1: J10_D5.2@50.88,111.76 Q10_D5.2
NetD10_D5_2: D10_D5.2 O10_D5.1 R11_D5.1 | length 8.1
  Top Layer w0.5: R11_D5.1 81.28,106.68 O10_D5.1
NetD10_D6_1: D10_D6.1 J10_D6.2 O10_D6.2 Q10_D6.2 | length 49.6
  Top Layer w0.5: Q10_D6.2 76.835,96.52 78.74,98.425 ; D10_D6.1 78.74,98.425 ; O10_D6.2 85.09,95.25 83.82,96.52 80.645,96.52 78.74,98.425
  Top Layer w1: J10_D6.2@50.88,96.52 Q10_D6.2
  Bottom Layer w1: J10_D6.2@50.88,96.52 Q10_D6.2
NetD10_D6_2: D10_D6.2 O10_D6.1 R11_D6.1 | length 8.1
  Top Layer w0.5: R11_D6.1 81.28,91.44 O10_D6.1
NetD10_D7_1: D10_D7.1 J10_D7.2 O10_D7.2 Q10_D7.2 | length 49.6
  Top Layer w0.5: Q10_D7.2 76.835,81.28 78.74,83.185 ; D10_D7.1 78.74,83.185 ; O10_D7.2 85.09,80.01 83.82,81.28 80.645,81.28 78.74,83.185
  Top Layer w1: J10_D7.2@50.88,81.28 Q10_D7.2
  Bottom Layer w1: J10_D7.2@50.88,81.28 Q10_D7.2
NetD10_D7_2: D10_D7.2 O10_D7.1 R11_D7.1 | length 8.1
  Top Layer w0.5: R11_D7.1 81.28,76.2 O10_D7.1
NetD11_D0_2: D11_D0.2 O10_D0.4 Q10_D0.1 R10_D0.1 R14_D0.1 R15_D0.2 | length 40.9
  Top Layer w0.5: R14_D0.1 R10_D0.1 139.065,74.295 142.24,74.295 143.51,75.565 ; O10_D0.4 143.51,75.565 ; Q10_D0.1 165.06,76.2 D11_D0.2 158.115,78.105 150.495,78.105 149.225,76.835 149.225,75.565 147.955,74.295 144.78,74.295 143.51,75.565
NetD11_D1_2: D11_D1.2 O10_D1.4 Q10_D1.1 R10_D1.1 R14_D1.1 R15_D1.2 | length 49.6
  Top Layer w0.5: R14_D1.1 134.62,97.79 137.16,95.25 R10_D1.1 139.065,89.535 142.24,89.535 143.51,90.805 ; O10_D1.4 143.51,90.805 ; Q10_D1.1 165.06,91.44 D11_D1.2 158.115,93.345 150.495,93.345 149.225,92.075 149.225,90.805 147.955,89.535 144.78,89.535 143.51,90.805
NetD11_D2_2: D11_D2.2 O10_D2.4 Q10_D2.1 R10_D2.1 R14_D2.1 R15_D2.2 | length 40.9
  Top Layer w0.5: Q10_D2.1 61,162.56 D11_D2.2 67.945,160.655 75.565,160.655 76.835,161.925 76.835,163.195 78.105,164.465 81.28,164.465 82.55,163.195 ; O10_D2.4 82.55,163.195 ; R14_D2.1 R10_D2.1 86.995,164.465 83.82,164.465 82.55,163.195
NetD11_D3_2: D11_D3.2 O10_D3.4 Q10_D3.1 R10_D3.1 R14_D3.1 R15_D3.2 | length 40.9
  Top Layer w0.5: Q10_D3.1 61,147.32 D11_D3.2 67.945,145.415 75.565,145.415 76.835,146.685 76.835,147.955 78.105,149.225 81.28,149.225 82.55,147.955 ; O10_D3.4 82.55,147.955 ; R14_D3.1 R10_D3.1 86.995,149.225 83.82,149.225 82.55,147.955
NetD11_D4_2: D11_D4.2 O10_D4.4 Q10_D4.1 R10_D4.1 R14_D4.1 R15_D4.2 | length 40.9
  Top Layer w0.5: Q10_D4.1 61,132.08 D11_D4.2 67.945,130.175 75.565,130.175 76.835,131.445 76.835,132.715 78.105,133.985 81.28,133.985 82.55,132.715 ; O10_D4.4 82.55,132.715 ; R14_D4.1 R10_D4.1 86.995,133.985 83.82,133.985 82.55,132.715
NetD11_D5_2: D11_D5.2 O10_D5.4 Q10_D5.1 R10_D5.1 R14_D5.1 R15_D5.2 | length 40.9
  Top Layer w0.5: Q10_D5.1 61,116.84 D11_D5.2 67.945,114.935 75.565,114.935 76.835,116.205 76.835,117.475 78.105,118.745 81.28,118.745 82.55,117.475 ; O10_D5.4 82.55,117.475 ; R14_D5.1 R10_D5.1 86.995,118.745 83.82,118.745 82.55,117.475
NetD11_D6_2: D11_D6.2 O10_D6.4 Q10_D6.1 R10_D6.1 R14_D6.1 R15_D6.2 | length 40.9
  Top Layer w0.5: Q10_D6.1 61,101.6 D11_D6.2 67.945,99.695 75.565,99.695 76.835,100.965 76.835,102.235 78.105,103.505 81.28,103.505 82.55,102.235 ; O10_D6.4 82.55,102.235 ; R14_D6.1 R10_D6.1 86.995,103.505 83.82,103.505 82.55,102.235
NetD11_D7_2: D11_D7.2 O10_D7.4 Q10_D7.1 R10_D7.1 R14_D7.1 R15_D7.2 | length 40.9
  Top Layer w0.5: Q10_D7.1 61,86.36 D11_D7.2 67.945,84.455 75.565,84.455 76.835,85.725 76.835,86.995 78.105,88.265 81.28,88.265 82.55,86.995 ; O10_D7.4 82.55,86.995 ; R14_D7.1 R10_D7.1 86.995,88.265 83.82,88.265 82.55,86.995
NetD30_2: D30.2 D31.1 | length 11.2
  Top Layer w0.5: D31.1 102.87,144.145 105.41,141.605 D30.2
NetD31_2: D31.2 O30.4 Q30.2 R34.1 | length 25.1
  Top Layer w0.5: D31.2 102.87,135.89 104.14,134.62 106.68,134.62 107.95,135.89 R34.1 113.03,142.24 116.84,142.24 O30.4
NetD34_2: D34.2 O31.1 R36.1 R39.2 | length 25.7
  Top Layer w0.5: R36.1 127,160.02 129.54,157.48 R39.2 D34.2
  Bottom Layer w0.5: D34.2 137.16,152.4 138.43,151.13 O31.1
NetD50_1: D50.1 J50.3 | length 14.9
  Top Layer w0.5: J50.3 52.865,177.64 59.69,170.815 D50.1
NetD50_2: D50.2 Q50.2 R50.2 | length 9.7
  Top Layer w0.5: D50.2 R50.2 Q50.2
NetD70_2: D70.2 R77.2 | length 35.4
  Top Layer w0.5: D70.2 101.6,74.93 122.555,74.93 125.73,78.105 127.635,78.105 R77.2
NetD71_2: D71.2 R78.2 | length 11.7
  Top Layer w0.5: D71.2 124.46,80.01 129.54,80.01 132.08,77.47 R78.2
NetJ10_D0_3: J10_D0.3 R11_D0.2 R12_D0.1 R13_D0.1 | length 25.8
  Top Layer w0.5: R11_D0.2 R12_D0.1 159.385,74.295 168.275,74.295 170.34,76.36 J10_D0.3
NetJ10_D1_3: J10_D1.3 R11_D1.2 R12_D1.1 R13_D1.1 | length 25.8
  Top Layer w0.5: R11_D1.2 R12_D1.1 159.385,89.535 168.275,89.535 170.34,91.6 J10_D1.3
NetJ10_D2_3: J10_D2.3 R11_D2.2 R12_D2.1 R13_D2.1 | length 25.8
  Top Layer w0.5: J10_D2.3 55.72,162.4 57.785,164.465 66.675,164.465 R12_D2.1 R11_D2.2
NetJ10_D3_3: J10_D3.3 R11_D3.2 R12_D3.1 R13_D3.1 | length 25.8
  Top Layer w0.5: J10_D3.3 55.72,147.16 57.785,149.225 66.675,149.225 R12_D3.1 R11_D3.2
NetJ10_D4_3: J10_D4.3 R11_D4.2 R12_D4.1 R13_D4.1 | length 25.8
  Top Layer w0.5: J10_D4.3 55.72,131.92 57.785,133.985 66.675,133.985 R12_D4.1 R11_D4.2
NetJ10_D5_3: J10_D5.3 R11_D5.2 R12_D5.1 R13_D5.1 | length 25.8
  Top Layer w0.5: J10_D5.3 55.72,116.68 57.785,118.745 66.675,118.745 R12_D5.1 R11_D5.2
NetJ10_D6_3: J10_D6.3 R11_D6.2 R12_D6.1 R13_D6.1 | length 25.8
  Top Layer w0.5: J10_D6.3 55.72,101.44 57.785,103.505 66.675,103.505 R12_D6.1 R11_D6.2
NetJ10_D7_3: J10_D7.3 R11_D7.2 R12_D7.1 R13_D7.1 | length 25.8
  Top Layer w0.5: J10_D7.3 55.72,86.2 57.785,88.265 66.675,88.265 R12_D7.1 R11_D7.2
NetJ20_A0_2: J20_A0.2 R22_A0.2 | length 17
  Top Layer w0.5: R22_A0.2 162.56,113.03 163.75,111.84 J20_A0.2
NetJ20_A0_3: J20_A0.3 R20_A0.1 R21_A0.1 | length 8.7
  Top Layer w0.5: R20_A0.1 J20_A0.3@175.1,106.68
NetJ20_A1_2: J20_A1.2 R22_A1.2 | length 17
  Top Layer w0.5: R22_A1.2 162.56,128.27 163.75,127.08 J20_A1.2
NetJ20_A1_3: J20_A1.3 R20_A1.1 R21_A1.1 | length 8.7
  Top Layer w0.5: R20_A1.1 J20_A1.3@175.1,121.92
NetJ20_A2_2: J20_A2.2 R22_A2.2 | length 17
  Top Layer w0.5: R22_A2.2 162.56,143.51 163.75,142.32 J20_A2.2
NetJ20_A2_3: J20_A2.3 R20_A2.1 R21_A2.1 | length 8.7
  Top Layer w0.5: R20_A2.1 J20_A2.3@175.1,137.16
NetJ20_A3_2: J20_A3.2 R22_A3.2 | length 17
  Top Layer w0.5: R22_A3.2 162.56,158.75 163.75,157.56 J20_A3.2
NetJ20_A3_3: J20_A3.3 R20_A3.1 R21_A3.1 | length 8.7
  Top Layer w0.5: R20_A3.1 J20_A3.3@175.1,152.4
NetJ30_3: J30.3 R32.1 | length 14.3
  Top Layer w0.5: J30.3 108.585,123.825 117.475,123.825 R32.1
NetJ70_5: J70.5 R71.2 R72.2 | length 14.1
  Top Layer w0.5: J70.5 129.54,99.06 R72.2
  Bottom Layer w0.5: J70.5 128.27,100.965 132.08,104.775 R71.2
NetO30_2: O30.2 R37.2 | length 11
  Top Layer w0.5: O30.2 128.27,143.51 R37.2
NetQ30_1: Q30.1 R33.1 | length 6.1
  Top Layer w0.5: R33.1 113.03,137.16 Q30.1
R\E\S\E\T\: R70.1 R71.1 S70.2 S70.4 U70.1 | length 39.4
  Top Layer w0.5: U70.1 109.855,120.015 117.475,120.015 120.65,116.84 R71.1 ; 130.47,116.84 S70.2
SCK: J70.3 J72.6 U70.19 | length 46.7
  Top Layer w0.5: U70.19 116.84,95.25 120.65,91.44 129.54,91.44 130.81,92.71 130.81,95.25 129.54,96.52 J70.3
  Bottom Layer w0.5: J72.6 109.855,84.455 109.855,90.805 114.3,95.25 U70.19
SCL: J71.9 J71.10 R75.1 U70.28 | length 95.3
  Top Layer w0.5: U70.28 117.475,118.11 120.65,114.935 132.715,114.935 140.97,123.19 140.97,162.56 133.985,169.545 125.095,169.545 J71.10 J71.9
SDA: J71.5 J71.6 R76.1 U70.27 | length 93.9
  Top Layer w0.5: U70.27 117.475,115.57 119.38,113.665 133.985,113.665 142.24,121.92 142.24,163.195 134.62,170.815 128.905,170.815 J71.6 J71.5
SS: J72.3 R72.1 U70.16 | length 31.1
  Bottom Layer w0.5: J72.3 113.665,80.645 113.665,86.995 114.3,87.63 125.73,87.63 129.54,91.44 R72.1
pads on no net: J30.2 J30.6 J50.2

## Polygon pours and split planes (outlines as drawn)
0V on Bottom Layer "Bottom Layer-No Net" (solid, remove dead copper, pour order 1000): 93.345,108.585 93.345,84.455 103.505,84.455 103.505,108.585

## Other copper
Top Layer:
  text "CONTROLLER-V1" at 109.22,166.37 h1.52

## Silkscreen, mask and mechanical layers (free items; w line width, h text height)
Top Overlay:
  text "VIN" at 38.1,177.165 h1.52
  text "GND" at 182.88,177.165 h1.52
  text "5V" at 182.88,172.085 h1.52
  text "GND" at 38.1,167.005 h1.52
  text "12V" at 182.88,167.005 h1.52
  text "VOUT" at 38.1,161.925 h1.52
  text "GND" at 182.88,161.925 h1.52
  text "DIG2" at 38.1,156.845 h1.52
  text "ADC3" at 182.88,156.845 h1.52
  text "GND" at 38.1,153.67 h1.52
  text "VOUT" at 182.88,153.67 h1.52
  text "VOUT" at 38.1,144.78 h1.52
  text "GND" at 182.88,144.78 h1.52
  text "DIG3" at 38.1,141.605 h1.52
  text "ADC2" at 182.88,141.605 h1.52
  text "GND" at 38.1,136.525 h1.52
  text "VOUT" at 182.88,136.525 h1.52
  text "GND" at 182.88,132.08 h1.52
  text "VOUT" at 38.1,131.445 h1.52
  text "DIG4" at 38.1,126.365 h1.52
  text "ADC1" at 182.88,126.365 h1.52
  text "GND" at 38.1,121.285 h1.52
  text "VOUT" at 182.88,121.285 h1.52
  text "VOUT" at 38.1,116.205 h1.52
  text "GND" at 182.88,116.205 h1.52
  text "DIG5" at 38.1,111.125 h1.52
  text "ADC0" at 182.88,111.125 h1.52
  text "GND" at 38.1,107.95 h1.52
  text "VOUT" at 182.88,107.95 h1.52
  text "VOUT" at 38.1,99.06 h1.52
  text "GND" at 182.88,99.06 h1.52
  text "DIG6" at 38.1,95.885 h1.52
  text "DIG1" at 182.88,95.885 h1.52
  text "GND" at 38.1,90.805 h1.52
  text "VOUT" at 182.88,90.805 h1.52
  text "VOUT" at 38.1,85.725 h1.52
  text "GND" at 182.88,85.725 h1.52
  text "DIG7" at 38.1,80.645 h1.52
  text "DIG0" at 182.88,80.645 h1.52
  text "GND" at 38.1,75.565 h1.52
  text "VOUT" at 182.88,75.565 h1.52
Mechanical 1:
  lines w0.3: 223.266,45.974 223.52,45.72 ; 35.56,71.12 190.5,71.12 190.5,182.88 35.56,182.88 35.56,71.12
